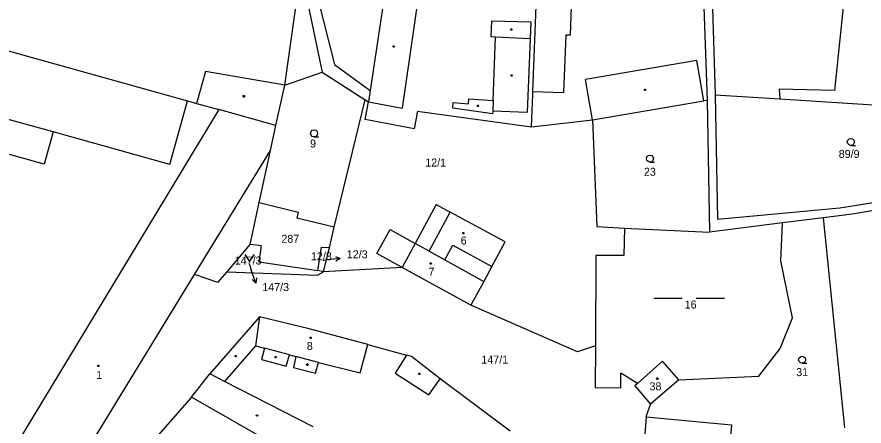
# Model space of a CAD drawing. Extents: x -752500 to -750336, y -1035826 to -1033500.
# Drawn here: x -751563.4 to -751383.4, y -1034390.2 to -1034303.4 of the extents above; entities that cross this region are included whole.
import ezdxf

# ---------------------------------------------------------------- set-up
doc = ezdxf.new("R2010")
doc.units = 0
for name, color, linetype in [('Default', 7, 'Continuous'), ('Hranice parcel', 7, 'Continuous'), ('Parcelní čísla', 7, 'Continuous'), ('Pop  PČ popisy', 7, 'Continuous'), ('Vnitřní kresba', 7, 'Continuous'), ('Značky budov', 7, 'Continuous'), ('Značky kultur', 7, 'Continuous')]:
    doc.layers.add(name, color=color, linetype=linetype)

# ---------------------------------------------------------------- blocks, each defined once
blk = doc.blocks.new('304')
at = {"layer": 'Default'}
blk.add_lwpolyline([(0, 0), (-0.38, 0.1), (-0.65, 0.37), (-0.75, 0.74), (-0.65, 1.11), (-0.38, 1.38), (-0.01, 1.48), (0.36, 1.38), (0.63, 1.11), (0.73, 0.73), (0.63, 0.35), (0.36, 0.08), (-0.02, -0.02), (0.98, -0.02)], dxfattribs=at)
blk = doc.blocks.new('314')
at = {"layer": 'Default'}
for p, q in [((-0.95, 0), (-0.85, 0)), ((0.85, 0), (0.95, 0))]:
    blk.add_line(p, q, dxfattribs=at)
blk.add_lwpolyline([(-1, 1.5), (0, 0), (1, 1.5)], dxfattribs=at)
blk = doc.blocks.new('803')
at = {"layer": 'Default'}
for p, q in [((-7.5, 0), (-1.5, 0)), ((1.5, 0), (7.5, 0))]:
    blk.add_line(p, q, dxfattribs=at)
blk = doc.blocks.new('10292')
at = {"layer": 'Default'}
blk.add_line((0, 3), (0, 0), dxfattribs=at)
blk.add_lwpolyline([(-0.5, 2), (0, 3), (0.5, 2)], dxfattribs=at)
blk = doc.blocks.new('402')
at = {"layer": 'Default'}
blk.add_lwpolyline([(0.09, 0.15), (0.18, 0), (0.09, -0.15), (-0.09, -0.15), (-0.18, 0), (-0.09, 0.15), (0.09, 0.15)], dxfattribs=at)

msp = doc.modelspace()

# ---------------------------------------------------------------- linework, layer by layer
at = {"layer": 'Hranice parcel'}
for p, q in [((-751383.59, -1034259.87), (-751389.73, -1034318.97)), ((-751500.36, -1034296.01), (-751495.96, -1034313.45)), ((-751453.83, -1034319.15), (-751452.93, -1034296.13)), ((-751415.84, -1034295.21), (-751415.11, -1034319.86)), ((-751502.37, -1034296.89), (-751498.62, -1034315.07)), ((-751485.15, -1034297.33), (-751488.39, -1034319)), ((-751506.55, -1034317.85), (-751503.74, -1034298.26)), ((-751417.55, -1034299.16), (-751416.76, -1034321.06)), ((-751495.96, -1034313.45), (-751488.39, -1034319)), ((-751506.55, -1034317.85), (-751498.62, -1034315.07)), ((-751498.62, -1034315.07), (-751489.46, -1034320.92)), ((-751508.41, -1034326.41), (-751506.55, -1034317.85)), ((-751488.39, -1034319), (-751488.74, -1034321.38)), ((-751453.86, -1034319.84), (-751453.83, -1034319.15)), ((-751389.73, -1034318.97), (-751401.46, -1034318.7)), ((-751401.46, -1034318.7), (-751401.38, -1034320.74)), ((-751496.01, -1034348), (-751489.46, -1034320.92)), ((-751489.46, -1034320.92), (-751488.74, -1034321.38)), ((-751489.45, -1034325.11), (-751488.74, -1034321.38)), ((-751454.13, -1034326.71), (-751453.86, -1034319.84)), ((-751441.17, -1034325.21), (-751417.52, -1034321.17)), ((-751416.76, -1034321.06), (-751417.52, -1034321.17)), ((-751416.76, -1034321.06), (-751416.26, -1034349.05)), ((-751415.11, -1034319.86), (-751414.6, -1034346.26)), ((-751415.11, -1034319.86), (-751401.38, -1034320.74)), ((-751401.38, -1034320.74), (-751346.88, -1034324.25)), ((-751478.33, -1034323.35), (-751479.03, -1034327.08)), ((-751478.33, -1034323.35), (-751471.21, -1034324.34)), ((-751471.21, -1034324.34), (-751454.13, -1034326.71)), ((-751509.56, -1034331.72), (-751508.41, -1034326.41)), ((-751479.03, -1034327.08), (-751489.45, -1034325.11)), ((-751454.13, -1034326.71), (-751441.17, -1034325.21)), ((-751441.17, -1034325.21), (-751440.2, -1034347.86)), ((-751511.95, -1034342.77), (-751509.56, -1034331.72)), ((-751388.63, -1034343.88), (-751349.38, -1034337.65)), ((-751349.22, -1034339.19), (-751386, -1034345.21)), ((-751513.87, -1034351.62), (-751511.95, -1034342.77)), ((-751511.95, -1034342.77), (-751503.68, -1034344.77)), ((-751503.68, -1034344.77), (-751504, -1034346.07)), ((-751474.36, -1034343.17), (-751478.83, -1034351.42)), ((-751474.36, -1034343.17), (-751471.4, -1034344.77)), ((-751459.71, -1034351.11), (-751471.4, -1034344.77)), ((-751414.6, -1034346.26), (-751388.63, -1034343.88)), ((-751496.01, -1034348), (-751504, -1034346.07)), ((-751392.08, -1034345.98), (-751400.77, -1034347.08)), ((-751386, -1034345.21), (-751392.08, -1034345.98)), ((-751387.54, -1034390.53), (-751392.08, -1034345.98)), ((-751497.04, -1034352.25), (-751496.01, -1034348)), ((-751440.2, -1034347.86), (-751434.38, -1034348.15)), ((-751434.38, -1034348.15), (-751434.49, -1034354.01)), ((-751434.38, -1034348.15), (-751416.26, -1034349.05)), ((-751400.77, -1034347.08), (-751416.26, -1034349.05)), ((-751401.1, -1034355.08), (-751400.77, -1034347.08)), ((-751486.96, -1034353.57), (-751484.14, -1034348.47)), ((-751484.14, -1034348.47), (-751478.83, -1034351.42)), ((-751518.8, -1034357.42), (-751513.87, -1034351.62)), ((-751511.59, -1034351.92), (-751513.87, -1034351.62)), ((-751511.59, -1034351.92), (-751512.04, -1034355.3)), ((-751475.89, -1034353.05), (-751478.83, -1034351.42)), ((-751462.54, -1034356.33), (-751459.71, -1034351.11)), ((-751499.48, -1034357.19), (-751498.77, -1034352.2)), ((-751498.77, -1034352.2), (-751497.04, -1034352.25)), ((-751498.29, -1034357.45), (-751497.04, -1034352.25)), ((-751481.59, -1034356.52), (-751486.96, -1034353.57)), ((-751475.89, -1034353.05), (-751472.53, -1034354.91)), ((-751512.04, -1034355.3), (-751499.48, -1034357.19)), ((-751472.53, -1034354.91), (-751464.25, -1034359.5)), ((-751440.42, -1034354.01), (-751440.53, -1034373.12)), ((-751434.49, -1034354.01), (-751440.42, -1034354.01)), ((-751398.69, -1034367.21), (-751401.1, -1034355.08)), ((-751498.29, -1034357.45), (-751499.48, -1034357.19)), ((-751481.59, -1034356.52), (-751498.29, -1034357.45)), ((-751466.98, -1034364.54), (-751481.59, -1034356.52)), ((-751462.54, -1034356.33), (-751464.25, -1034359.5)), ((-751528.27, -1034362.22), (-751525.7, -1034358.03)), ((-751520.75, -1034359.71), (-751525.7, -1034358.03)), ((-751520.75, -1034359.71), (-751518.8, -1034357.42)), ((-751518.8, -1034357.42), (-751499.62, -1034358.18)), ((-751499.62, -1034358.18), (-751498.29, -1034357.45)), ((-751464.25, -1034359.5), (-751466.98, -1034364.54)), ((-751556.65, -1034408.47), (-751528.27, -1034362.22)), ((-751444.37, -1034374.44), (-751466.98, -1034364.54)), ((-751511.94, -1034366.97), (-751522.48, -1034379.1)), ((-751501.38, -1034369.57), (-751511.94, -1034366.97)), ((-751401.28, -1034373.72), (-751398.69, -1034367.21)), ((-751488.87, -1034372.9), (-751501.38, -1034369.57)), ((-751488.87, -1034372.9), (-751480.67, -1034375.14)), ((-751440.53, -1034373.12), (-751444.37, -1034374.44)), ((-751440.53, -1034373.12), (-751440.58, -1034381.96)), ((-751479.61, -1034375.43), (-751480.67, -1034375.14)), ((-751405.83, -1034379.6), (-751401.28, -1034373.72)), ((-751473.53, -1034380.16), (-751479.61, -1034375.43)), ((-751426.26, -1034376.44), (-751431.61, -1034381.16)), ((-751422.79, -1034380.38), (-751426.26, -1034376.44)), ((-751435.12, -1034382.08), (-751435.1, -1034378.93)), ((-751431.61, -1034381.16), (-751435.1, -1034378.93)), ((-751526.33, -1034384.01), (-751522.48, -1034379.1)), ((-751458.62, -1034391.29), (-751473.53, -1034380.16)), ((-751422.79, -1034380.38), (-751428.82, -1034385.56)), ((-751422.79, -1034380.38), (-751405.83, -1034379.6)), ((-751440.58, -1034381.96), (-751435.12, -1034382.08)), ((-751431.61, -1034381.16), (-751432.17, -1034381.66)), ((-751432.17, -1034381.66), (-751428.82, -1034385.56)), ((-751526.33, -1034384.01), (-751536.85, -1034395.95)), ((-751503.65, -1034396.98), (-751526.33, -1034384.01)), ((-751429.76, -1034388.21), (-751428.82, -1034385.56)), ((-751429.76, -1034388.21), (-751430.17, -1034393.66)), ((-751429.76, -1034388.21), (-751411.64, -1034389.95)), ((-751411.64, -1034389.95), (-751412.05, -1034395.4))]:
    msp.add_line(p, q, dxfattribs=at)
at = {"layer": 'Pop  PČ popisy'}
for p, q in [((-751498.41, -1034354.99), (-751497.73, -1034354.92)), ((-751514.04, -1034355.9), (-751513.67, -1034356.99))]:
    msp.add_line(p, q, dxfattribs=at)
at = {"layer": 'Vnitřní kresba'}
for p, q in [((-751445.52, -1034296.8), (-751445.93, -1034307.23)), ((-751478.09, -1034298.35), (-751481.6, -1034322.73)), ((-751600.51, -1034300.74), (-751527.21, -1034321.17)), ((-751462.69, -1034307.61), (-751462.54, -1034304.15)), ((-751462.54, -1034304.15), (-751454.23, -1034304.41)), ((-751454.23, -1034304.41), (-751454.43, -1034308.03)), ((-751461.74, -1034307.66), (-751462.69, -1034307.61)), ((-751462.27, -1034321.1), (-751461.74, -1034307.66)), ((-751454.43, -1034308.03), (-751461.74, -1034307.66)), ((-751454.43, -1034308.03), (-751455.01, -1034323.66)), ((-751446.82, -1034307.2), (-751447.3, -1034319.41)), ((-751445.93, -1034307.23), (-751446.82, -1034307.2)), ((-751418.98, -1034312.62), (-751442.63, -1034316.65)), ((-751417.52, -1034321.17), (-751418.98, -1034312.62)), ((-751523.4, -1034314.95), (-751525.28, -1034321.71)), ((-751506.55, -1034317.85), (-751523.4, -1034314.95)), ((-751441.17, -1034325.21), (-751442.63, -1034316.65)), ((-751453.83, -1034319.15), (-751447.3, -1034319.41)), ((-751530.96, -1034334.65), (-751527.21, -1034321.17)), ((-751527.21, -1034321.17), (-751525.28, -1034321.71)), ((-751488.74, -1034321.38), (-751481.6, -1034322.73)), ((-751467.52, -1034321.77), (-751467.45, -1034320.73)), ((-751467.45, -1034320.73), (-751462.27, -1034321.1)), ((-751462.27, -1034321.1), (-751462.36, -1034323.33)), ((-751520.57, -1034323.02), (-751580.81, -1034422.5)), ((-751555.76, -1034327.75), (-751572.59, -1034323.07)), ((-751525.28, -1034321.71), (-751520.57, -1034323.02)), ((-751508.41, -1034326.41), (-751520.57, -1034323.02)), ((-751470.83, -1034322.7), (-751470.76, -1034321.5)), ((-751462.39, -1034323.93), (-751470.83, -1034322.7)), ((-751470.76, -1034321.5), (-751467.52, -1034321.77)), ((-751462.36, -1034323.33), (-751462.39, -1034323.93)), ((-751455.01, -1034323.66), (-751462.36, -1034323.33)), ((-751555.76, -1034327.75), (-751557.68, -1034334.62)), ((-751530.96, -1034334.65), (-751555.76, -1034327.75)), ((-751557.68, -1034334.62), (-751574.51, -1034329.93)), ((-751525.7, -1034358.03), (-751509.56, -1034331.72)), ((-751475.89, -1034353.05), (-751471.4, -1034344.77)), ((-751478.83, -1034351.42), (-751481.59, -1034356.52)), ((-751472.53, -1034354.91), (-751470.81, -1034351.78)), ((-751470.81, -1034351.78), (-751462.54, -1034356.33)), ((-751511.94, -1034366.97), (-751512.78, -1034373.15)), ((-751512.78, -1034373.15), (-751519.38, -1034380.69)), ((-751512.78, -1034373.15), (-751510.84, -1034373.66)), ((-751490.51, -1034378.9), (-751488.87, -1034372.9)), ((-751510.84, -1034373.66), (-751511.48, -1034376.08)), ((-751505.55, -1034375.05), (-751510.84, -1034373.66)), ((-751506.26, -1034377.45), (-751505.55, -1034375.05)), ((-751505.55, -1034375.05), (-751504.16, -1034375.41)), ((-751480.67, -1034375.14), (-751483.05, -1034378.92)), ((-751511.48, -1034376.08), (-751506.26, -1034377.45)), ((-751504.16, -1034375.41), (-751504.65, -1034377.75)), ((-751499.39, -1034376.67), (-751504.16, -1034375.41)), ((-751500.02, -1034378.95), (-751499.39, -1034376.67)), ((-751499.39, -1034376.67), (-751490.51, -1034378.9)), ((-751504.65, -1034377.75), (-751500.02, -1034378.95)), ((-751483.05, -1034378.92), (-751475.91, -1034383.58)), ((-751519.38, -1034380.69), (-751522.48, -1034379.1)), ((-751500.54, -1034390.33), (-751519.38, -1034380.69)), ((-751475.91, -1034383.58), (-751473.53, -1034380.16))]:
    msp.add_line(p, q, dxfattribs=at)

# ---------------------------------------------------------------- block references
at = {"layer": 'Pop  PČ popisy'}
for p, rotation in [((-751497.73, -1034354.92), -83.77704700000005), ((-751513.67, -1034356.99), -161.29823700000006)]:
    msp.add_blockref('10292', p, dxfattribs=dict(at, rotation=rotation))
at = {"layer": 'Značky budov'}
for p in [(-751458.4, -1034306.02), (-751483.4, -1034309.63), (-751458.36, -1034315.78), (-751429.97, -1034318.81), (-751515.24, -1034320.21), (-751465.52, -1034322.21), (-751468.58, -1034349.26), (-751475.54, -1034355.7), (-751501.05, -1034371.45), (-751516.95, -1034375.35), (-751508.5, -1034375.53), (-751501.73, -1034377.15), (-751546.15, -1034377.37), (-751477.96, -1034379.07), (-751427.39, -1034380.12), (-751512.45, -1034387.94)]:
    msp.add_blockref('402', p, dxfattribs=at)
at = {"layer": 'Značky kultur'}
for name, p in [('304', (-751500.31, -1034328.8)), ('304', (-751386.26, -1034330.62)), ('304', (-751428.93, -1034334.16)), ('314', (-751514, -1034355.27)), ('803', (-751420.63, -1034363.06)), ('304', (-751396.6, -1034376.84))]:
    msp.add_blockref(name, p, dxfattribs=at)

# ---------------------------------------------------------------- texts
at = {"layer": 'Parcelní čísla'}
for s, p in [('9', (-751501.16, -1034331.07)), ('89/9', (-751388.83, -1034333.27)), ('12/1', (-751476.69, -1034335.11)), ('23', (-751430.23, -1034337.06)), ('287', (-751507.26, -1034351.28)), ('6', (-751469.16, -1034351.66)), ('12/3', (-751500.97, -1034354.99)), ('12/3', (-751493.36, -1034354.59)), ('147/3', (-751517.17, -1034355.9)), ('7', (-751476, -1034358.26)), ('147/3', (-751511.32, -1034361.53)), ('16', (-751421.56, -1034365.24)), ('8', (-751501.85, -1034374.03)), ('147/1', (-751464.77, -1034376.93)), ('1', (-751546.61, -1034380.18)), ('31', (-751397.87, -1034379.58)), ('38', (-751429.03, -1034382.59))]:
    msp.add_text(s, height=1.7, dxfattribs=at).set_placement(p)

doc.saveas('drawing.dxf')
